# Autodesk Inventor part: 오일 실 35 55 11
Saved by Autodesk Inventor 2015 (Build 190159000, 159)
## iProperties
Created: 2025-06
Part Number: 오일 실 35 55 11
Material: 일반
Document SubType Name: Modeling
Designer: User
Density: 1 g/cm^3
Appearance: 기본값
Author: User
Author: jhkim
Description: 오일 실 - 비스프링, 조립 GA
Creation Date: 2025-05-23
Sending System: Autodesk Inventor 2026
Preprocessor: ST-DEVELOPER v20.1
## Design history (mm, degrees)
node "오일 실 35 55 111"
body "Solid1"
node "기준1"
